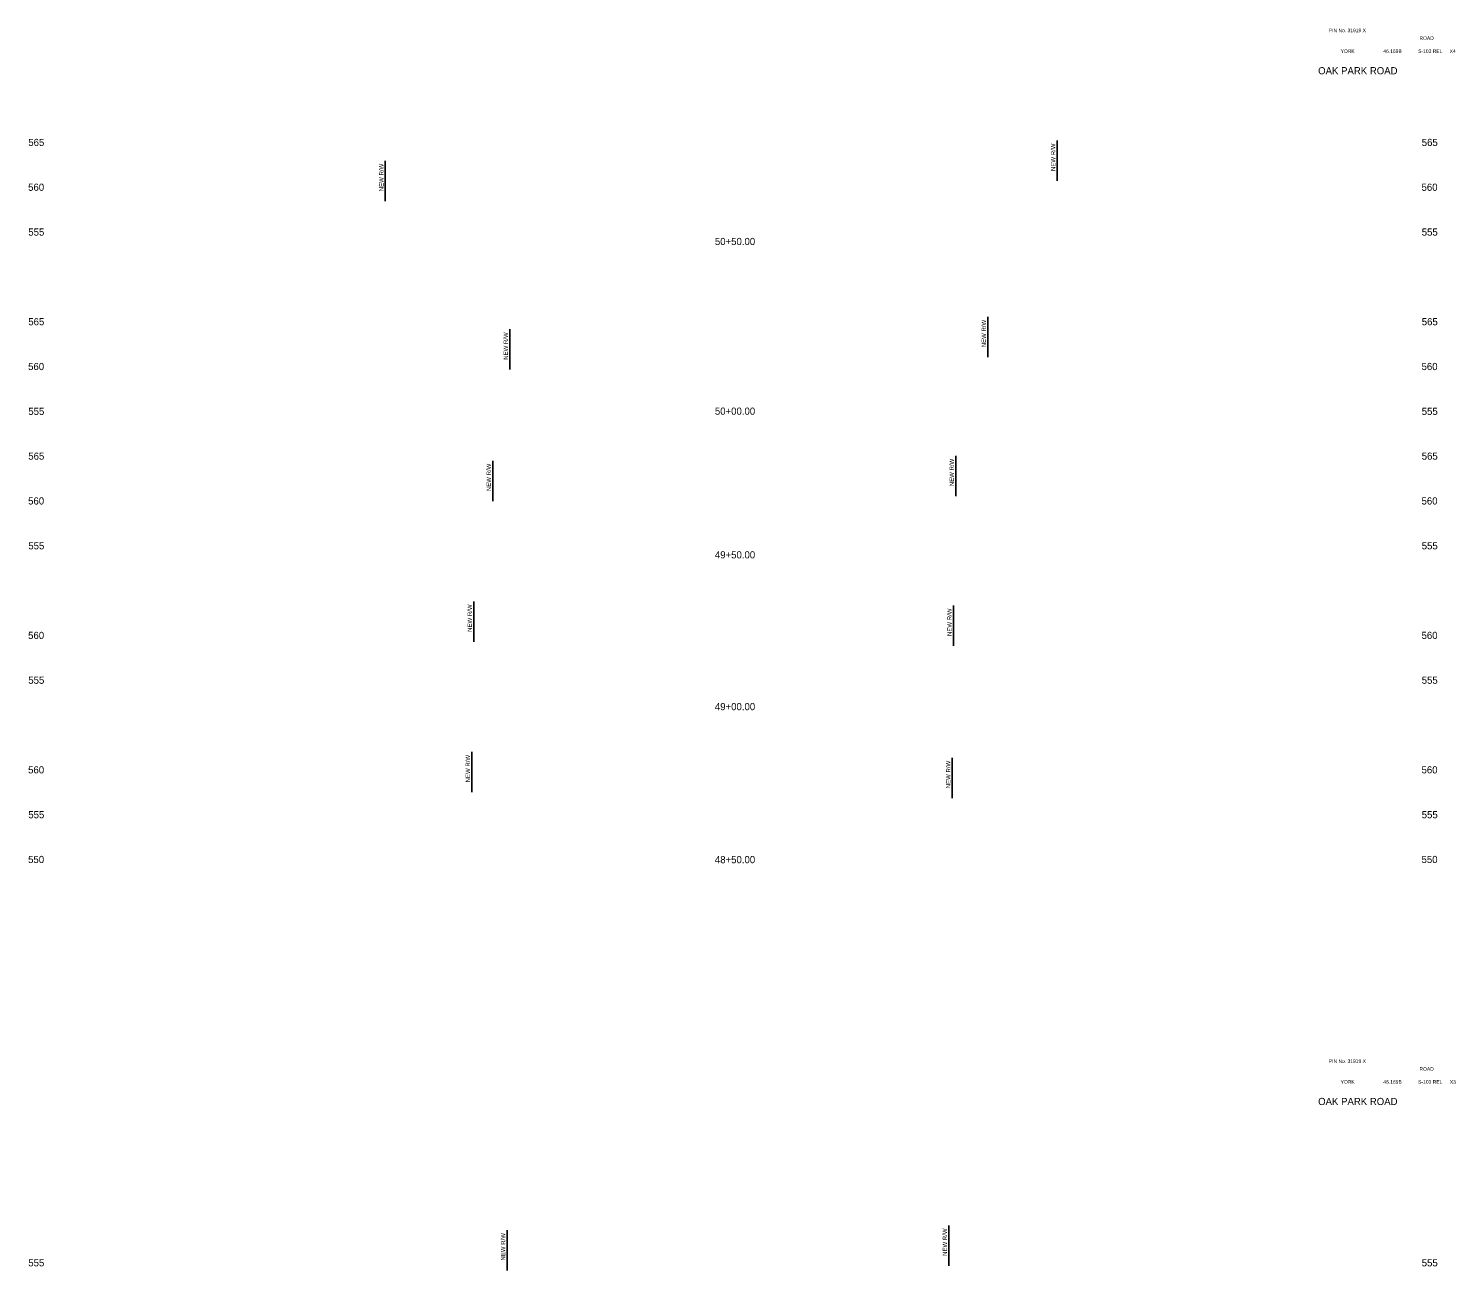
# Model space of a CAD drawing. Extents: x 1001 to 1161, y 1005 to 3518.
# Drawn here: x 1001.2 to 1160.4, y 1309.6 to 1448.2 of the extents above; entities that cross this region are included whole.
import ezdxf

# ---------------------------------------------------------------- set-up
doc = ezdxf.new("R2010")
doc.units = 0
for name, color, linetype in [('RD_SHT_TX', 7, 'Continuous'), ('RD_XS_NewRW', 7, 'Continuous'), ('RD_XS_TX_Elev_EX', 7, 'Continuous'), ('RD_XS_TX_Station', 7, 'Continuous')]:
    doc.layers.add(name, color=color, linetype=linetype)

msp = doc.modelspace()

# ---------------------------------------------------------------- linework, layer by layer
at = {"layer": 'RD_XS_NewRW'}
for p, q in [((1115.97, 1435.71), (1115.97, 1431.21)), ((1041, 1433.45), (1041, 1428.95)), ((1108.23, 1416.04), (1108.23, 1411.54)), ((1054.88, 1414.65), (1054.88, 1410.15)), ((1053, 1399.99), (1053, 1395.49)), ((1104.65, 1400.54), (1104.65, 1396.04)), ((1050.86, 1384.29), (1050.86, 1379.79)), ((1104.41, 1383.83), (1104.41, 1379.33)), ((1050.65, 1367.5), (1050.65, 1363)), ((1104.27, 1366.84), (1104.27, 1362.34)), ((1054.58, 1314.14), (1054.58, 1309.64)), ((1103.89, 1314.67), (1103.89, 1310.17))]:
    msp.add_line(p, q, dxfattribs=at)

# ---------------------------------------------------------------- texts
at = {"layer": 'RD_SHT_TX'}
for s, height, p in [('PIN No. 31919 X', 0.4, (1146.29, 1447.8)), ('YORK', 0.4, (1147.61, 1445.48)), ('46.169B', 0.4, (1152.37, 1445.48)), ('S-103 REL', 0.4, (1156.26, 1445.48)), ('ROAD', 0.4, (1156.41, 1446.93)), ('X4', 0.4, (1159.78, 1445.48)), ('OAK PARK ROAD', 0.8, (1145.1, 1443.1)), ('PIN No. 31919 X', 0.4, (1146.29, 1332.8)), ('ROAD', 0.4, (1156.41, 1331.93)), ('YORK', 0.4, (1147.61, 1330.48)), ('46.169B', 0.4, (1152.37, 1330.48)), ('S-103 REL', 0.4, (1156.26, 1330.48)), ('X3', 0.4, (1159.79, 1330.48)), ('OAK PARK ROAD', 0.8, (1145.1, 1328.1))]:
    msp.add_text(s, height=height, dxfattribs=at).set_placement(p)
at = {"layer": 'RD_XS_NewRW'}
for p in [(1115.77, 1432.31), (1040.8, 1430.05), (1054.68, 1411.25), (1108.03, 1412.64), (1104.45, 1397.14), (1052.79, 1396.59), (1050.66, 1380.89), (1104.21, 1380.43), (1050.45, 1364.1), (1104.07, 1363.44), (1054.38, 1310.75), (1103.69, 1311.27)]:
    msp.add_text('NEW R/W ', height=0.488, rotation=90, dxfattribs=at).set_placement(p)
at = {"layer": 'RD_XS_TX_Elev_EX'}
for s, p in [('565', (1001.16, 1435.1)), ('565', (1156.66, 1435.1)), ('560', (1001.14, 1430.1)), ('560', (1156.64, 1430.1)), ('555', (1001.16, 1425.1)), ('555', (1156.66, 1425.1)), ('565', (1001.16, 1415.1)), ('565', (1156.66, 1415.1)), ('560', (1001.14, 1410.1)), ('560', (1156.64, 1410.1)), ('555', (1001.16, 1405.1)), ('555', (1156.66, 1405.1)), ('565', (1001.16, 1400.1)), ('565', (1156.66, 1400.1)), ('560', (1001.14, 1395.1)), ('560', (1156.64, 1395.1)), ('555', (1001.16, 1390.1)), ('555', (1156.66, 1390.1)), ('560', (1001.14, 1380.1)), ('560', (1156.64, 1380.1)), ('555', (1001.16, 1375.1)), ('555', (1156.66, 1375.1)), ('560', (1001.14, 1365.1)), ('560', (1156.64, 1365.1)), ('555', (1001.16, 1360.1)), ('555', (1156.66, 1360.1)), ('550', (1001.14, 1355.1)), ('550', (1156.64, 1355.1)), ('555', (1001.16, 1310.1)), ('555', (1156.66, 1310.1))]:
    msp.add_text(s, height=0.8, dxfattribs=at).set_placement(p)
at = {"layer": 'RD_XS_TX_Station'}
for s, p in [('50+50.00', (1077.78, 1424.05)), ('50+00.00', (1077.78, 1405.12)), ('49+50.00', (1077.78, 1389.09)), ('49+00.00', (1077.78, 1372.15)), ('48+50.00', (1077.78, 1355.08))]:
    msp.add_text(s, height=0.8, dxfattribs=at).set_placement(p)

doc.saveas('drawing.dxf')
